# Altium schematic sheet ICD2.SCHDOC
size Letter; SheetNumber: 1; SheetTotal: 1
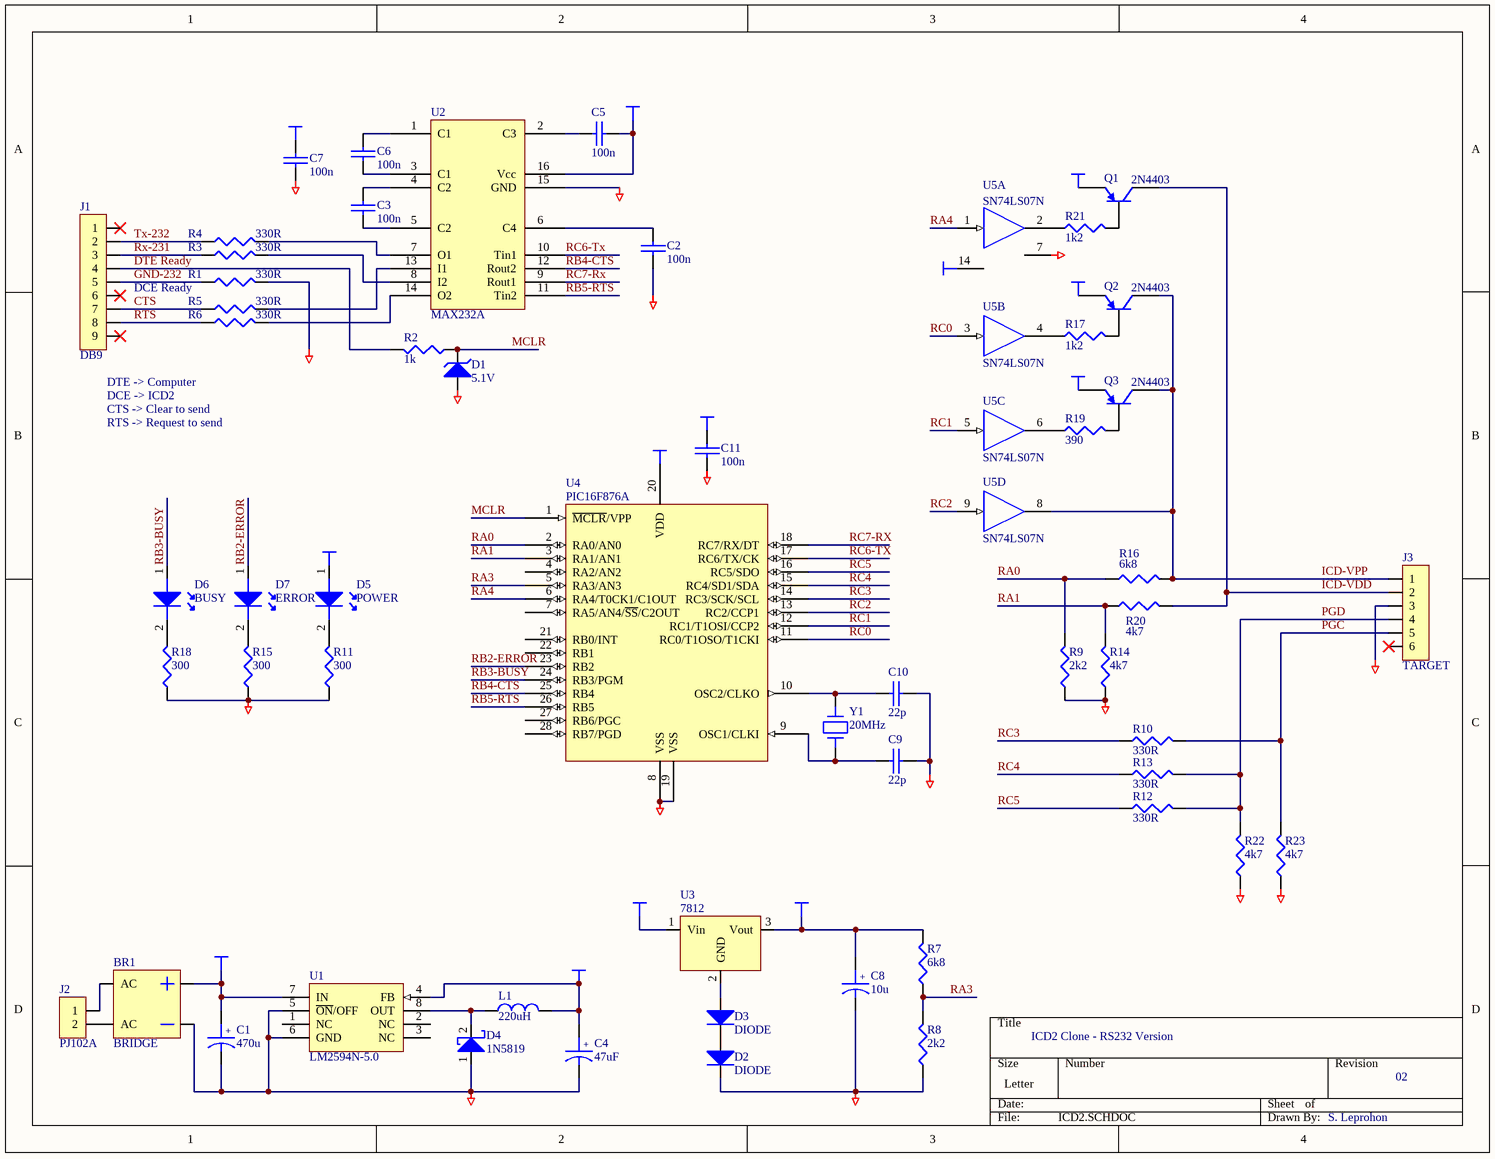
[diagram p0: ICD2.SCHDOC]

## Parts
BR1  BRIDGE  [BRIDGE/DIP4]
C1  470u  [CPCYL1/D.400/LS.200/.037]
C2  100n  [RAD/.300X.100/LS.200/.032]
C3  100n  [RAD/.300X.100/LS.200/.032]
C4  47uF  [CPCYL1/D.250/LS.125/.032]
C5  100n  [RAD/.300X.100/LS.200/.032]
C6  100n  [RAD/.300X.100/LS.200/.032]
C7  100n  [RAD/.300X.100/LS.200/.032]
C8  10u  [CPCYL1/D.200/LS.100/.032]
C9  22p  [RAD/.300X.100/LS.200/.032]
C10  22p  [RAD/.300X.100/LS.200/.032]
C11  100n  [RAD/.300X.100/LS.200/.032]
D1  5.1V  [DAX2/.400X.080/.032]
D2  DIODE  [DAX2/.400X.080/.032]
D3  DIODE  [DAX2/.400X.080/.032]
D4  1N5819  [DAX2/.425X.100/.041]
D5  POWER  [LED/ROND/5MM]
D6  BUSY  [LED/ROND/5MM]
D7  ERROR  [LED/ROND/5MM]
J1  DB9  [DSUB/RS.318/TM/9]
J2  PJ102A  [DC_POWER_JACK]
J3  TARGET  [JACK1.27-2V6A]
L1  220uH  [CYL/D.400/LS.200/.037]
Q1  2N4403  [TO92/100]
Q2  2N4403  [TO92/100]
Q3  2N4403  [TO92/100]
R1  330R  [AX/.400X.100/.032]
R2  1k  [AX/.400X.100/.032]
R3  330R  [AX/.400X.100/.032]
R4  330R  [AX/.400X.100/.032]
R5  330R  [AX/.400X.100/.032]
R6  330R  [AX/.400X.100/.032]
R7  6k8  [AX/.400X.100/.032]
R8  2k2  [AX/.400X.100/.032]
R9  2k2  [AX/.400X.100/.032]
R10  330R  [AX/.400X.100/.032]
R11  300  [AX/.400X.100/.032]
R12  330R  [AX/.400X.100/.032]
R13  330R  [AX/.400X.100/.032]
R14  4k7  [AX/.400X.100/.032]
R15  300  [AX/.400X.100/.032]
R16  6k8  [AX/.400X.100/.032]
R17  1k2  [AX/.400X.100/.032]
R18  300  [AX/.400X.100/.032]
R19  390  [AX/.400X.100/.032]
R20  4k7  [AX/.400X.100/.032]
R21  1k2  [AX/.400X.100/.032]
R22  4k7  [AX/.400X.100/.032]
R23  4k7  [AX/.400X.100/.032]
U1  LM2594N-5.0  [DIP.100/8/W.300/L.425]
U2  MAX232A  [DIP.100/16/W.300/L.800]
U3  7812  [TO220AB/VF1]
U4  PIC16F876A  [DIP.100/28/W.300/L1.425]
U5  SN74LS07N  [DIP.100/14/W.300/L.750]  (parts A,B,C,D of 6)
Y1  20MHz  [XTAL/HC49]

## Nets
+V: BR1.V+ C1.1 U1.7(IN) U3.1(Vin)
GND: BR1.V- C1.2 C2.2 C4.2 C7.2 C8.2 C9.2 C10.2 C11.2 D1.1(A) D2.2(K) D4.1(A) J3.3 R1.2 R8.1 R9.1 R11.1 R14.1 R15.1 R18.1 R22.1 R23.1 U1.5(~{ON}/OFF) U1.6(GND) U2.15(GND) U4.8(VSS) U4.19(VSS) U5.7(GND)
VCC: C4.1 C5.2 C7.1 C11.1 D5.1(A) L1.2 Q1.1(E) Q3.1(E) U1.4(FB) U2.16(Vcc) U4.20(VDD) U5.14(VCC)
VPP: C8.1 Q2.1(E) R7.2 U3.3(Vout)
CTS: J1.7 R5.1
DTE Ready: J1.4 R2.2
GND-232: J1.5 R1.1
ICD-VDD: J3.2 Q1.3(C) R20.2
ICD-VPP: J3.1 Q2.3(C) Q3.3(C) R16.2 U5.8(Y)
MCLR: D1.2(K) R2.1 U4.1(~{MCLR}/VPP)
PGC: J3.5 R10.2 R23.2
PGD: J3.4 R12.2 R13.2 R22.2
RA0: R9.2 R16.1 U4.2(RA0/AN0)
RA1: R14.2 R20.1 U4.3(RA1/AN1)
RA3: R7.1 R8.2 U4.5(RA3/AN3)
RA4: U4.6(RA4/T0CK1/C1OUT) U5.1(A)
RB2-ERROR: D7.1(A) U4.23(RB2)
RB3-BUSY: D6.1(A) U4.24(RB3/PGM)
RB4-CTS: U2.12(Rout2) U4.25(RB4)
RB5-RTS: U2.11(Tin2) U4.26(RB5)
RC0: U4.11(RC0/T1OSO/T1CKI) U5.3(A)
RC1: U4.12(RC1/T1OSI/CCP2) U5.5(A)
RC2: U4.13(RC2/CCP1) U5.9(A)
RC3: R10.1 U4.14(RC3/SCK/SCL)
RC4: R13.1 U4.15(RC4/SD1/SDA)
RC5: R12.1 U4.16(RC5/SDO)
RC6-Tx: U2.10(Tin1) U4.17(RC6/TX/CK)
RC7-Rx: U2.9(Rout1) U4.18(RC7/RX/DT)
RTS: J1.8 R6.1
Rx-231: J1.3 R3.1
Tx-232: J1.2 R4.1
NetBR1_AC1: BR1.AC1(AC) J2.2
NetBR1_AC2: BR1.AC2(AC) J2.1
NetC2_1: C2.1 U2.6(C4)
NetC3_1: C3.1 U2.4(C2)
NetC3_2: C3.2 U2.5(C2)
NetC5_1: C5.1 U2.2(C3)
NetC6_1: C6.1 U2.1(C1)
NetC6_2: C6.2 U2.3(C1)
NetC9_1: C9.1 U4.9(OSC1/CLKI) Y1.2
NetC10_1: C10.1 U4.10(OSC2/CLKO) Y1.1
NetD2_1: D2.1(A) D3.2(K)
NetD3_1: D3.1(A) U3.2(GND)
NetD4_2: D4.2(K) L1.1 U1.8(OUT)
NetD5_2: D5.2(K) R11.2
NetD6_2: D6.2(K) R18.2
NetD7_2: D7.2(K) R15.2
NetQ1_2: Q1.2(B) R21.2
NetQ2_2: Q2.2(B) R17.2
NetQ3_2: Q3.2(B) R19.2
NetR3_2: R3.2 U2.8(I2)
NetR4_2: R4.2 U2.7(O1)
NetR5_2: R5.2 U2.13(I1)
NetR6_2: R6.2 U2.14(O2)
NetR17_1: R17.1 U5.4(Y)
NetR19_1: R19.1 U5.6(Y)
NetR21_1: R21.1 U5.2(Y)

Not connected (* = marked no-connect by the designer): J1 1* 6* 9*; J3 6*; U1 1(NC) 2(NC) 3(NC); U4 4(RA2/AN2) 7(RA5/AN4/~{SS}/C2OUT) 21(RB0/INT) 22(RB1) 27(RB6/PGC) 28(RB7/PGD)

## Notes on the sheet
- DCE Ready
- DTE -> Computer
- DCE -> ICD2
- CTS -> Clear to send
- RTS -> Request to send
- ICD2 Clone - RS232 Version
- 02
- S. Leprohon

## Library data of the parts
BR1 = BRIDGE: PONT DE DIODE
C1 C4 C8 = CE: CONDO ELECT POLARISE DE BASE
C2 C3 C5-C7 C9-C11 = CC: CONDO CERAMIQUE DE BASE
D1 = ZENER: DIODE ZENER
D4 = SCHOTTKY: DIODE SCHOTTKY
D5-D7 = LED: LED RONDE OU RECTANGULAIRE
J1 = CON9: CONNECTEUR 9 PINS
J2 = CON2: CONNECTEUR 2 PINS
J3 = CON6: CONNECTEUR 6 PINS
L1 = INDUCTANCE: Part Number: M6023-ND
Q1-Q3 = 2N3906: PNP General Purpose Amplifier; Manufacturer: Generic Components; Revised: 11-July-2000: SIM Model Added.; Class: Discrete; SubClass: BJT - Low Power
R1-R23 = R1/4W: RESISTANCE 1/4W LS=.4"
U1 = LM2594N-5.0: Simple Switcher Power Converter 150 kHz 0.5A Step Down Voltage Regulator; Manufacturer: National Semiconductor; Class: Power Management; SubClass: Switching Regulator
U2 = MAX232: Part Field 1: 0; Part Field 10: 10u
U3 = REG/POS/TO220: REGULATEUR POSITIF TO220
U5 = SN74LS07N: Hex Buffer / Driver with Open-Collector High-Voltage Outputs; Manufacturer: Texas Instruments; Class: Logic; SubClass: Gate
Y1 = CRYSTAL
